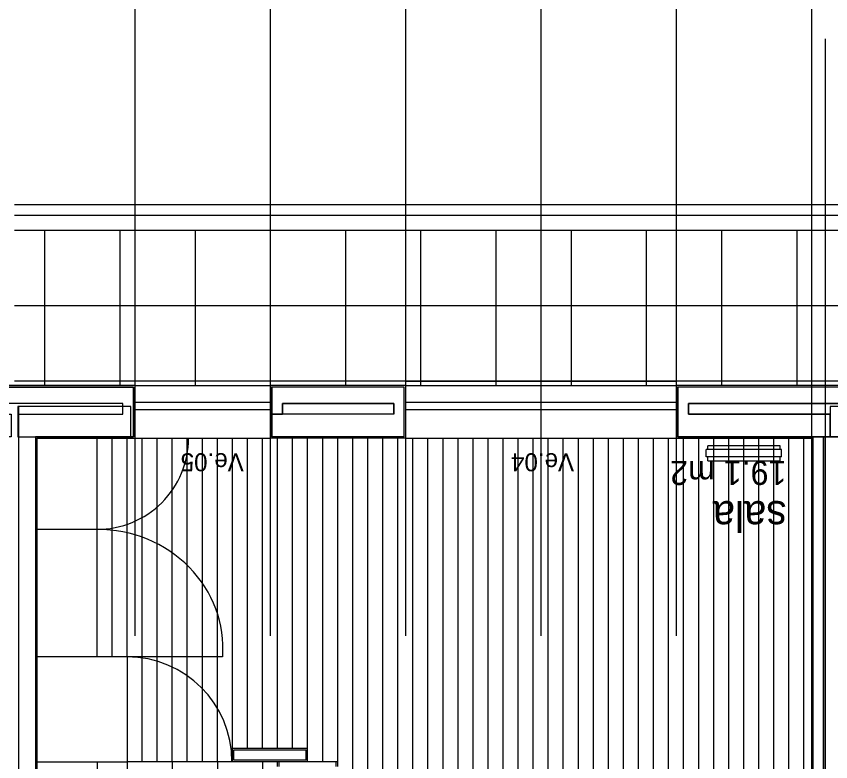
# Model space of a CAD drawing. Extents: x 1248 to 1356, y -443 to -224.
# Drawn here: x 1323.9 to 1329.32, y -234.42 to -229.47 of the extents above; entities that cross this region are included whole.
import ezdxf

# ---------------------------------------------------------------- set-up
doc = ezdxf.new("R2010")
doc.units = 0
for name, color, linetype in [('corte', 7, 'Continuous'), ('estereoctomias', 7, 'Continuous'), ('Level 1', 7, 'Continuous'), ('Level 10', 7, 'Continuous'), ('Level 13', 7, 'Continuous'), ('Level 2', 7, 'Continuous'), ('Level 3', 7, 'Continuous'), ('Level 4', 7, 'Continuous'), ('Level 40', 7, 'Continuous'), ('Level 60', 7, 'Continuous'), ('revestimentos', 7, 'Continuous'), ('vermelhos-cont', 7, 'Continuous'), ('vermelhos-tracej', 7, 'Continuous')]:
    doc.layers.add(name, color=color, linetype=linetype)

msp = doc.modelspace()

# ---------------------------------------------------------------- linework, layer by layer
at = {"layer": 'corte'}
for p, q in [((1324.684, -231.934), (1322.907, -231.934)), ((1326.484, -231.934), (1325.604, -231.934)), ((1330.084, -231.934), (1328.304, -231.934)), ((1324.614, -232.044), (1322.977, -232.044)), ((1323.9218, -238.544), (1323.9218, -232.0639)), ((1326.414, -232.044), (1325.674, -232.044)), ((1330.0125, -232.044), (1328.374, -232.044)), ((1326.414, -232.114), (1325.674, -232.114)), ((1328.374, -232.114), (1329.3168, -232.114)), ((1326.484, -232.264), (1325.604, -232.264)), ((1329.4325, -232.264), (1328.304, -232.264)), ((1329.2018, -238.424), (1329.2018, -232.264)), ((1329.2718, -236.7713), (1329.2718, -232.264)), ((1328.9925, -232.349), (1328.4925, -232.349)), ((1328.4925, -232.399), (1328.4925, -232.349)), ((1328.9825, -232.324), (1328.5025, -232.324)), ((1328.5025, -232.349), (1328.5025, -232.324)), ((1328.9825, -232.349), (1328.9825, -232.324)), ((1328.9925, -232.399), (1328.9925, -232.349)), ((1328.9925, -232.399), (1328.4925, -232.399)), ((1328.5025, -232.424), (1328.5025, -232.399)), ((1328.9825, -232.424), (1328.9825, -232.399)), ((1328.5025, -232.424), (1328.9825, -232.424))]:
    msp.add_line(p, q, dxfattribs=at)
for points in [[(1324.666, -232.0639), (1323.916, -232.0639), (1323.916, -232.2657), (1324.666, -232.2657)], [(1330.0668, -232.0639), (1329.3168, -232.0639), (1329.3168, -232.2657), (1330.0668, -232.2657)]]:
    msp.add_lwpolyline(points, close=True, dxfattribs=at)
at = {"layer": 'estereoctomias'}
for points in [[(1323.9218, -235.8713), (1323.9218, -232.114), (1324.614, -232.114), (1324.614, -232.044), (1322.977, -232.044), (1322.977, -232.114), (1322.977, -232.114), (1323.871, -232.114), (1323.871, -232.264), (1322.907, -232.264), (1322.907, -231.934), (1324.684, -231.934), (1324.684, -232.264), (1324.0318, -232.264), (1324.0318, -235.8713)], [(1326.484, -232.264), (1326.484, -231.934), (1325.604, -231.934), (1325.604, -232.114), (1325.674, -232.114), (1325.674, -232.044), (1326.414, -232.044), (1326.414, -232.114), (1325.604, -232.114), (1325.604, -232.264)], [(1330.084, -232.264), (1330.084, -231.934), (1328.304, -231.934), (1328.304, -232.264), (1329.3168, -232.264), (1329.3168, -232.114), (1328.374, -232.114), (1328.374, -232.044), (1330.0125, -232.044), (1330.0125, -232.079), (1330.0668, -232.079), (1330.0668, -232.2657)], [(1329.2718, -232.264), (1329.2718, -235.8713), (1329.2018, -235.8713), (1329.2018, -232.264)], [(1325.8318, -234.344), (1325.8318, -234.414), (1325.3518, -234.414), (1325.3518, -234.344)]]:
    msp.add_lwpolyline(points, close=True, dxfattribs=at)
at = {"layer": 'Level 1'}
for p, q in [((1324.684, -232.264), (1324.684, -231.934)), ((1325.604, -231.934), (1325.604, -232.264)), ((1326.484, -232.264), (1326.484, -231.934)), ((1328.304, -231.934), (1328.304, -232.264)), ((1324.614, -232.114), (1324.614, -232.044)), ((1325.674, -232.044), (1325.674, -232.114)), ((1326.414, -232.114), (1326.414, -232.044)), ((1328.374, -232.044), (1328.374, -232.114)), ((1323.9218, -232.114), (1323.9218, -232.114)), ((1324.0318, -232.264), (1324.684, -232.264)), ((1324.0318, -232.264), (1324.0318, -238.544)), ((1329.2018, -232.264), (1329.2018, -238.424)), ((1325.3518, -234.414), (1325.3518, -234.344)), ((1325.3518, -234.344), (1325.8318, -234.344)), ((1325.8318, -234.414), (1325.8318, -234.344)), ((1325.8318, -234.414), (1325.3518, -234.414)), ((1326.0418, -234.424), (1325.3418, -234.424)), ((1325.6418, -234.456), (1325.6418, -234.424)), ((1325.6518, -234.456), (1325.6518, -234.424)), ((1326.0318, -234.456), (1326.0318, -234.424)), ((1326.0418, -234.456), (1326.0418, -234.424))]:
    msp.add_line(p, q, dxfattribs=at)
at = {"layer": 'Level 10'}
for p, q in [((1329.2933, -230.894), (1323.8933, -230.894)), ((1324.0933, -230.894), (1324.0933, -231.924)), ((1324.5933, -230.894), (1324.5933, -231.924)), ((1325.0933, -230.894), (1325.0933, -231.924)), ((1325.5933, -230.894), (1325.5933, -231.924)), ((1326.0933, -230.894), (1326.0933, -231.924)), ((1326.5933, -230.894), (1326.5933, -231.924)), ((1327.0933, -230.894), (1327.0933, -231.924)), ((1327.5933, -230.894), (1327.5933, -231.924)), ((1328.0933, -230.894), (1328.0933, -231.924)), ((1328.5933, -230.894), (1328.5933, -231.924)), ((1329.0933, -230.894), (1329.0933, -231.924)), ((1334.6933, -230.894), (1329.2933, -230.894)), ((1329.2933, -231.394), (1323.8933, -231.394)), ((1334.6933, -231.394), (1329.2933, -231.394)), ((1329.2933, -231.894), (1323.8933, -231.894)), ((1326.4918, -231.894), (1328.2918, -231.894)), ((1334.6933, -231.894), (1329.2933, -231.894)), ((1324.5418, -233.727), (1324.5418, -232.274)), ((1324.6418, -233.727), (1324.6418, -232.274)), ((1324.7418, -234.424), (1324.7418, -232.274)), ((1324.8418, -234.424), (1324.8418, -232.274)), ((1324.9418, -234.424), (1324.9418, -232.274)), ((1325.0418, -234.424), (1325.0418, -232.274)), ((1325.1418, -234.424), (1325.1418, -232.274)), ((1325.2418, -234.424), (1325.2418, -232.274)), ((1325.3418, -234.334), (1325.3418, -232.274)), ((1325.4418, -234.334), (1325.4418, -232.274)), ((1325.5418, -234.334), (1325.5418, -232.274)), ((1325.6418, -234.334), (1325.6418, -232.274)), ((1325.7418, -234.334), (1325.7418, -232.274)), ((1325.8418, -234.334), (1325.8418, -232.274)), ((1325.9418, -234.424), (1325.9418, -232.274)), ((1326.0418, -234.424), (1326.0418, -232.274)), ((1326.1418, -238.414), (1326.1418, -232.274)), ((1326.2418, -238.414), (1326.2418, -232.274)), ((1326.3418, -238.414), (1326.3418, -232.274)), ((1326.4418, -238.414), (1326.4418, -232.274)), ((1326.5418, -238.414), (1326.5418, -232.274)), ((1326.6418, -238.414), (1326.6418, -232.274)), ((1326.7418, -236.624), (1326.7418, -232.274)), ((1326.8418, -236.624), (1326.8418, -232.274)), ((1326.9418, -236.624), (1326.9418, -232.274)), ((1327.0418, -236.624), (1327.0418, -232.274)), ((1327.1418, -236.624), (1327.1418, -232.274)), ((1327.2418, -236.624), (1327.2418, -232.274)), ((1327.3418, -236.624), (1327.3418, -232.274)), ((1327.4418, -236.624), (1327.4418, -232.274)), ((1327.5418, -236.624), (1327.5418, -232.274)), ((1327.6418, -236.624), (1327.6418, -232.274)), ((1327.7418, -236.624), (1327.7418, -232.274)), ((1327.8418, -236.624), (1327.8418, -232.274)), ((1327.9418, -236.624), (1327.9418, -232.274)), ((1328.0418, -236.624), (1328.0418, -232.274)), ((1328.1418, -236.624), (1328.1418, -232.274)), ((1328.2418, -236.624), (1328.2418, -232.274)), ((1328.3418, -236.624), (1328.3418, -232.274)), ((1328.4418, -236.624), (1328.4418, -232.274)), ((1328.5418, -236.624), (1328.5418, -232.274)), ((1328.6418, -236.624), (1328.6418, -232.274)), ((1328.7418, -236.624), (1328.7418, -232.274)), ((1328.8418, -236.624), (1328.8418, -232.274)), ((1328.9418, -236.624), (1328.9418, -232.274)), ((1329.0418, -236.624), (1329.0418, -232.274)), ((1329.1418, -236.624), (1329.1418, -232.274)), ((1325.3418, -234.424), (1324.6448, -234.424)), ((1324.9418, -234.424), (1324.9418, -236.824)), ((1325.2418, -234.424), (1325.2418, -236.824)), ((1325.5418, -234.424), (1325.5418, -236.824))]:
    msp.add_line(p, q, dxfattribs=at)
at = {"layer": 'Level 13'}
for p, q in [((1324.4418, -233.727), (1324.4418, -232.274)), ((1324.6418, -233.727), (1324.0418, -233.727)), ((1324.6418, -233.727), (1324.6418, -236.824))]:
    msp.add_line(p, q, dxfattribs=at)
at = {"layer": 'Level 2'}
for p, q in [((1329.2933, -230.724), (1323.8933, -230.724)), ((1334.6933, -230.724), (1329.2933, -230.724)), ((1329.2933, -230.794), (1323.8933, -230.794)), ((1334.6933, -230.794), (1329.2933, -230.794)), ((1324.694, -231.924), (1325.594, -231.924)), ((1326.494, -231.924), (1328.294, -231.924)), ((1324.694, -232.034), (1325.594, -232.034)), ((1324.694, -232.084), (1325.594, -232.084)), ((1326.494, -232.034), (1328.294, -232.034)), ((1326.494, -232.084), (1328.294, -232.084)), ((1324.694, -232.274), (1325.594, -232.274)), ((1326.494, -232.274), (1328.294, -232.274))]:
    msp.add_line(p, q, dxfattribs=at)
at = {"layer": 'Level 3'}
for q in [(1324.4418, -235.634), (1324.6418, -234.424)]:
    msp.add_line((1324.4418, -234.424), q, dxfattribs=at)
at = {"layer": 'Level 4'}
for p, q in [((1324.4418, -232.88), (1324.0418, -232.88)), ((1325.2768, -233.727), (1324.4418, -233.727)), ((1324.0418, -234.424), (1324.4418, -234.424))]:
    msp.add_line(p, q, dxfattribs=at)
msp.add_arc((1324.6418, -234.424), 0.697, 0, 90, dxfattribs=at)
for centre, major_axis, ratio, start_param, end_param in [((1324.4418, -232.274), (-0.6083, 0), 0.996291, 1.570796, 3.141593), ((1324.4418, -233.6703), (-0.8372, 0), 0.943954, 3.069792, 4.712389)]:
    msp.add_ellipse(centre, major_axis=major_axis, ratio=ratio, start_param=start_param, end_param=end_param, dxfattribs=at)
at = {"layer": 'revestimentos'}
for p, q in [((1324.694, -231.924), (1322.897, -231.924)), ((1324.694, -232.274), (1324.694, -231.924)), ((1325.594, -231.924), (1325.594, -232.274)), ((1326.494, -231.924), (1325.594, -231.924)), ((1326.494, -232.274), (1326.494, -231.924)), ((1330.094, -231.924), (1328.294, -231.924)), ((1328.294, -231.924), (1328.294, -232.274)), ((1324.0418, -232.274), (1324.0418, -236.824)), ((1324.0418, -232.274), (1324.694, -232.274)), ((1326.494, -232.274), (1325.594, -232.274)), ((1328.294, -232.274), (1329.1918, -232.274)), ((1329.1918, -232.274), (1329.1918, -238.414)), ((1325.3418, -234.334), (1325.8418, -234.334)), ((1325.3418, -234.424), (1325.3418, -234.334)), ((1325.8418, -234.424), (1325.8418, -234.334))]:
    msp.add_line(p, q, dxfattribs=at)
at = {"layer": 'vermelhos-cont'}
msp.add_line((1329.284, -250.7923), (1329.284, -229.6198), dxfattribs=at)
at = {"layer": 'vermelhos-tracej'}
for p, q in [((1324.694, -233.587), (1324.694, -228.3936)), ((1325.594, -233.587), (1325.594, -228.3936)), ((1326.494, -233.587), (1326.494, -228.3936)), ((1327.394, -233.587), (1327.394, -228.3936)), ((1328.294, -233.587), (1328.294, -228.3936)), ((1329.194, -233.587), (1329.194, -228.3936))]:
    msp.add_line(p, q, dxfattribs=at)

# ---------------------------------------------------------------- texts
at = {"layer": 'Level 40'}
for s, p in [('Ve.05', (1325.4171, -232.3738)), ('Ve.04', (1327.6133, -232.3738))]:
    msp.add_text(s, height=0.12, rotation=180, dxfattribs=at).set_placement(p)
at = {"layer": 'Level 60'}
for s, height, p in [('19.1 m2', 0.16, (1329.0254, -232.4246)), ('sala', 0.2, (1329.0254, -232.6924))]:
    msp.add_text(s, height=height, rotation=180, dxfattribs=at).set_placement(p)

doc.saveas('drawing.dxf')
